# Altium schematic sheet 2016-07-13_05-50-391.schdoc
size 387 x 177 mm; SheetNumber: 1; SheetTotal: 1
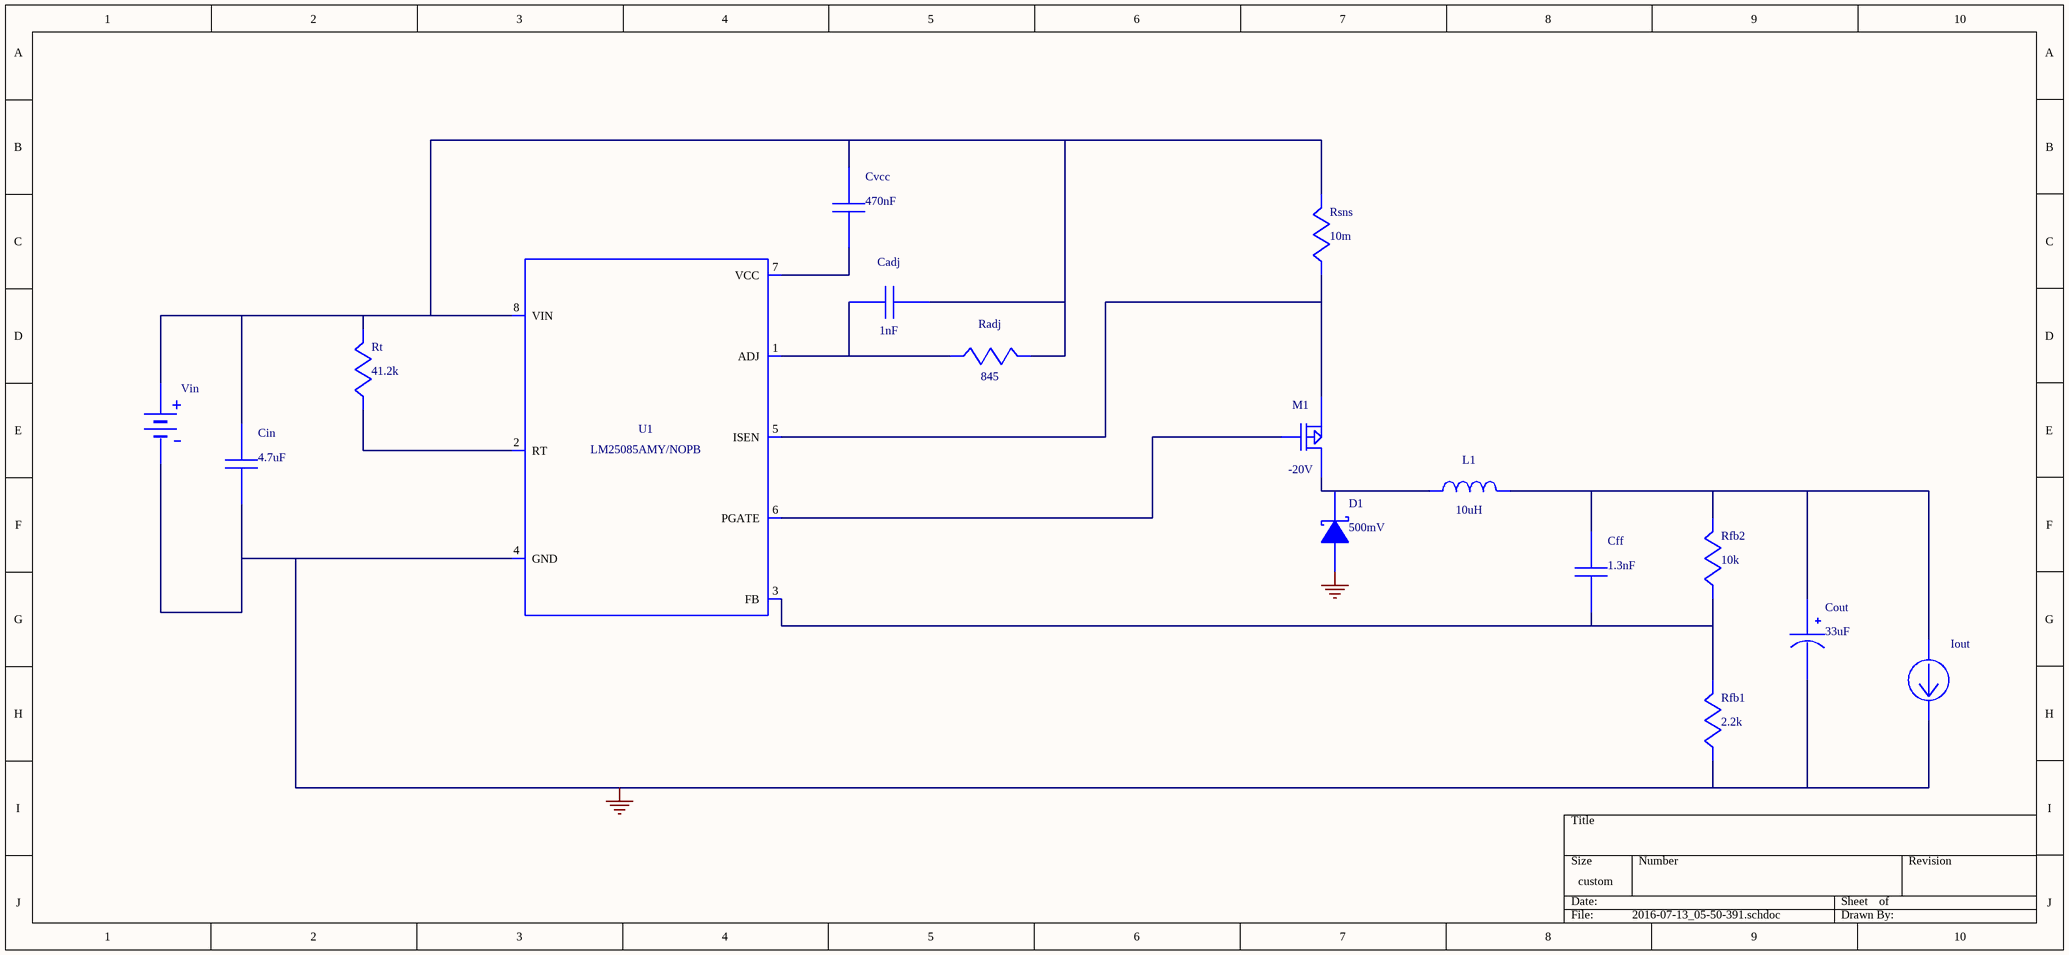
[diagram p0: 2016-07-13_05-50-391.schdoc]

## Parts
Cadj  value 1nF  (hidden comment: CL21C102JBCNFNC)
Cff  value 1.3nF  (hidden comment: 04025C132KAT2A)
Cin  value 4.7uF  (hidden comment: GRM21BC81E475KA12L)
Cout  value 33uF  (hidden comment: 293D336X9010C2TE3)
Cvcc  value 470nF  (hidden comment: 0805YC474KAT2A)
D1  value 500mV  (hidden comment: B220-13-F)
Iout  WB_CURRENT_LOAD  (value not drawn)
L1  value 10uH  (hidden comment: SRN6045-100M)
M1  value -20V  (hidden comment: CSD25402Q3A)
Radj  value 845  (hidden comment: CRCW0402845RFKED)
Rfb1  value 2.2k  (hidden comment: RC0603FR-072K2L)
Rfb2  value 10k  (hidden comment: CRCW040210K0FKED)
Rsns  value 10m  (hidden comment: CSR1206FK10L0)
Rt  value 41.2k  (hidden comment: CRCW040241K2FKED)
U1  LM5085MY/NOPB  (value not drawn)
Vin  WB_BATTERY  (value not drawn)

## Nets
0: Cin.2 Cout.2(-) D1.2(A) Iout.2(-) Rfb1.2 U1.4(GND) U1.9(EP) Vin.2(-)
NetCadj_1: Cadj.1 Cin.1 Cvcc.1 Radj.1 Rsns.1 Rt.1 U1.8(VIN) Vin.1(+)
NetCadj_2: Cadj.2 Radj.2 U1.1(ADJ)
NetCff_1: Cff.1 Cout.1(+) Iout.1(+) L1.2 Rfb2.1
NetCff_2: Cff.2 Rfb1.1 Rfb2.2 U1.3(FB)
NetCvcc_2: Cvcc.2 U1.7(VCC)
NetD1_1: D1.1(K) L1.1 M1.1(D) M1.2(D) M1.3(D)
NetM1_4: M1.4(G) U1.6(PGATE)
NetM1_5: M1.5(S) M1.6(S) M1.7(S) M1.8(S) M1.9(S) Rsns.2 U1.5(ISEN)
NetRt_2: Rt.2 U1.2(RT)

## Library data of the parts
Cadj = CL21C102JBCNFNC: Manufacturer Name: Samsung Electro-Mechanics
Cff = 04025C132KAT2A: Manufacturer Name: AVX
Cin = GRM21BC81E475KA12L: GRM21BC81E475KA1; Manufacturer Name: MuRata
Cout = 293D336X9010C2TE3: 293D336X9010C2TE; Manufacturer Name: Vishay-Sprague
Cvcc = 0805YC474KAT2A: Manufacturer Name: AVX
D1 = B220-13-F: Manufacturer Name: Diodes Inc.
L1 = SRN6045-100M: Manufacturer Name: Bourns
M1 = CSD25402Q3A: Manufacturer Name: Texas Instruments
Radj = CRCW0402845RFKED: Manufacturer Name: Vishay-Dale
Rfb1 = RC0603FR-072K2L: Manufacturer Name: Yageo America
Rfb2 = CRCW040210K0FKED: Manufacturer Name: Vishay-Dale
Rsns = CSR1206FK10L0: Manufacturer Name: Stackpole Electronics Inc
Rt = CRCW040241K2FKED: Manufacturer Name: Vishay-Dale
U1 = LM5085MY/NOPB: LM25085AMY/NOPB; Manufacturer Name: Texas Instruments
